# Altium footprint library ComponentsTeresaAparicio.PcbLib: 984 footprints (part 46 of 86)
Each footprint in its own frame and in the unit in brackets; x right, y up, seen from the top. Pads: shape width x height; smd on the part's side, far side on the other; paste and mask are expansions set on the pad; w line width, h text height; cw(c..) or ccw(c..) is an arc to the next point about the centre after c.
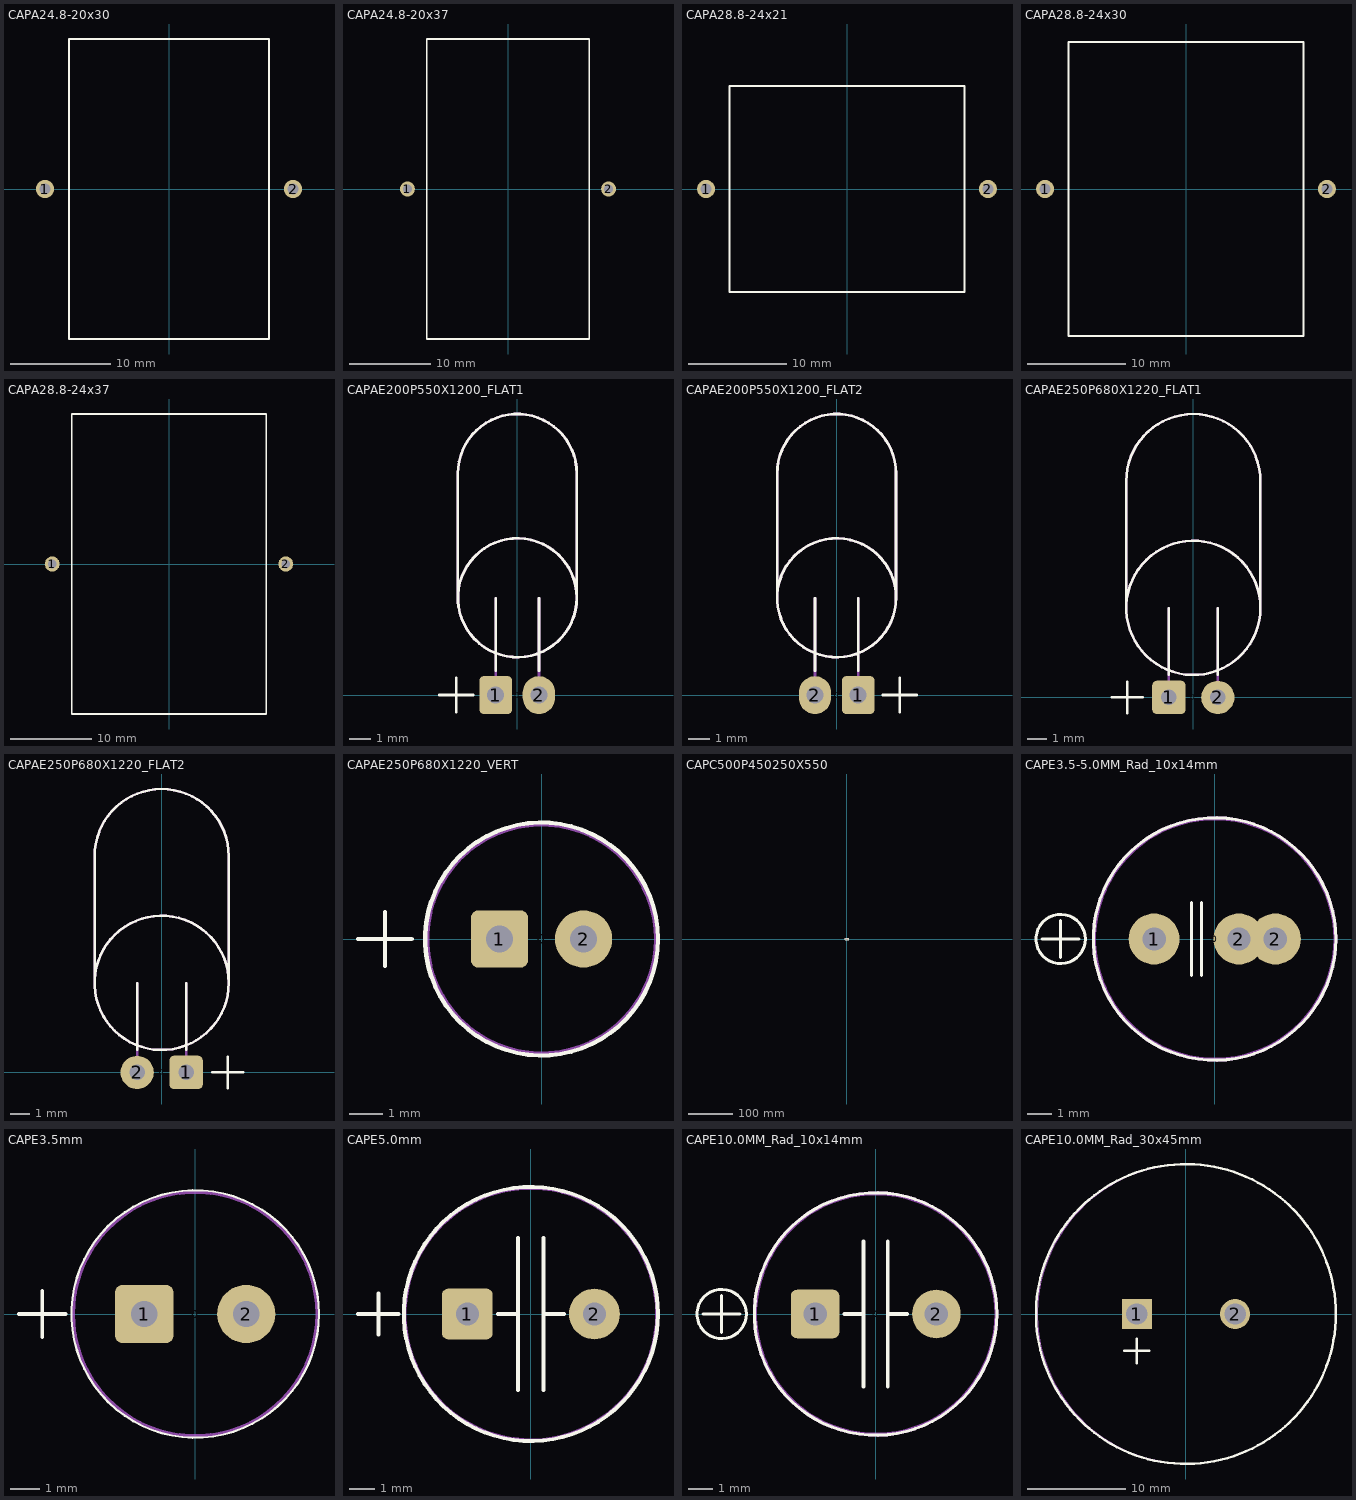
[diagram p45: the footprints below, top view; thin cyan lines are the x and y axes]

## CAPA24.8-20x30 [mm] "Capacitor, Ceramic, Thru-Hole, Axial Leads; Body 20 x 30 mm (LxDia. max) Pin Spacing 24.8 mm (typ)"
height 30
pads (2):
  round 1.85 hole 1.1: 1(-12.4,0) 2(12.4,0)
Top Overlay:
  lines w0.2: -10,-15 10,-15 10,15 -10,15 -10,-15

## CAPA24.8-20x37 [mm] "Capacitor, Ceramic, Thru-Hole, Axial Leads; Body 20 x 37 mm (LxDia. max) Pin Spacing 24.8 mm (typ)"
height 37
pads (2):
  round 1.85 hole 1.1: 1(-12.4,0) 2(12.4,0)
Top Overlay:
  lines w0.2: -10,-18.5 10,-18.5 10,18.5 -10,18.5 -10,-18.5

## CAPA28.8-24x21 [mm] "Capacitor, Ceramic, Thru-Hole, Axial Leads; Body 24 x 21 mm (LxDia. max) Pin Spacing 28.8 mm (typ)"
height 21
pads (2):
  round 1.85 hole 1.1: 1(-14.4,0) 2(14.4,0)
Top Overlay:
  lines w0.2: -12,-10.5 -12,10.5 12,10.5 12,-10.5 -12,-10.5

## CAPA28.8-24x30 [mm] "Capacitor, Ceramic, Thru-Hole, Axial Leads; Body 24 x 30 mm (LxDia. max) Pin Spacing 28.8 mm (typ)"
height 30
pads (2):
  round 1.85 hole 1.1: 1(-14.4,0) 2(14.4,0)
Top Overlay:
  lines w0.2: -12,-15 12,-15 12,15 -12,15 -12,-15

## CAPA28.8-24x37 [mm] "Capacitor, Ceramic, Thru-Hole, Axial Leads; Body 24 x 37 mm (LxDia. max) Pin Spacing 28.8 mm (typ)"
height 37
pads (2):
  round 1.85 hole 1.1: 1(-14.4,0) 2(14.4,0)
Top Overlay:
  lines w0.2: -12,-18.5 -12,18.5 12,18.5 12,-18.5 -12,-18.5

## CAPAE200P550X1200_FLAT1 [mil]
height 216.54
pads (3):
  round 20 on Mech14: 0(0,0)
  rrect25% 60x70 hole 31.5: 1(-40,0)
  oval 60x70 hole 31.5: 2(40,0)
Top Overlay:
  circle w5: c0,180 r110
  lines w5: -144.57,0 -81.57,0 ; -113.07,-31.5 -113.07,31.5 ; -110,180 -110,410 cw(c0,410) 110,410 110,180 ; -40,45 -40,179.21 ; 40,45 40,179.21
Mechanical 13:
  circle w5: c0,180 r110
  lines w5: -110,180 -110,410 cw(c0,410) 110,410 110,180 ; -40,0 -40,179.21 ; 40,0 40,179.21
3D body: height 215.69, standoff -70, extent -107.37,-9.82 107.35,502.05

## CAPAE200P550X1200_FLAT2 [mil]
height 216.54
pads (3):
  round 20 on Mech14: 0(0,0)
  rrect25% 60x70 hole 31.5: 1(40,0)
  oval 60x70 hole 31.5: 2(-40,0)
Top Overlay:
  circle w5: c0,180 r110
  lines w5: -110,180 -110,410 cw(c0,410) 110,410 110,180 ; -40,45 -40,179.21 ; 40,45 40,179.21 ; 85.43,0 148.43,0 ; 116.93,-31.5 116.93,31.5
Mechanical 13:
  circle w5: c0,180 r110
  lines w5: -110,180 -110,410 cw(c0,410) 110,410 110,180 ; -40,0 -40,179.21 ; 40,0 40,179.21
3D body: height 215.69, standoff -70, extent -107.33,-9.82 107.39,502.05

## CAPAE250P680X1220_FLAT1 [mm]
height 6.8
pads (3):
  round 0.508 on Mech14: 0(0,0)
  rrect25% 1.7x1.7 hole 0.8: 1(-1.25,0)
  round 1.7 hole 0.8: 2(1.25,0)
Top Overlay:
  circle w0.127: c0,4.572 r3.429
  lines w0.127: -4.18,0 -2.58,0 ; -3.429,4.572 -3.429,11.049 cw(c0,11.049) 3.429,11.049 3.429,4.572 ; -3.38,-0.8 -3.38,0.8 ; -1.25,1.143 -1.25,4.552 ; 1.25,1.143 1.25,4.552
Mechanical 13:
  circle w0.127: c0,4.572 r3.429
  lines w0.127: -3.429,4.572 -3.429,11.049 cw(c0,11.049) 3.429,11.049 3.429,4.572 ; -1.25,0 -1.25,4.552 ; 1.25,0 1.25,4.552
3D body: height 6.77, standoff -1.78, extent -3.372,-0.249 3.371,12.952

## CAPAE250P680X1220_FLAT2 [mm]
height 6.8
pads (3):
  round 0.508 on Mech14: 0(0,0)
  rrect25% 1.7x1.7 hole 0.8: 1(1.25,0)
  round 1.7 hole 0.8: 2(-1.25,0)
Top Overlay:
  circle w0.127: c0,4.572 r3.429
  lines w0.127: -3.429,4.572 -3.429,11.049 cw(c0,11.049) 3.429,11.049 3.429,4.572 ; -1.25,1.143 -1.25,4.552 ; 1.25,1.143 1.25,4.552 ; 2.58,0 4.18,0 ; 3.38,-0.8 3.38,0.8
Mechanical 13:
  circle w0.127: c0,4.572 r3.429
  lines w0.127: -3.429,4.572 -3.429,11.049 cw(c0,11.049) 3.429,11.049 3.429,4.572 ; -1.25,0 -1.25,4.552 ; 1.25,0 1.25,4.552
3D body: height 6.77, standoff -1.78, extent -3.371,-0.249 3.372,12.952

## CAPAE250P680X1220_VERT [mm]
height 12.2
pads (3):
  round 0.508 on Mech14: 0(0,0)
  rrect25% 1.7x1.7 hole 0.8: 1(-1.25,0)
  round 1.7 hole 0.8: 2(1.25,0)
Top Overlay:
  circle w0.127: c0,0 r3.459
  lines w0.127: -5.45,0 -3.85,0 ; -4.65,-0.8 -4.65,0.8
Mechanical 13:
  circle w0.127: c0,0 r3.4
3D body: height 12.2, standoff -1.78, extent -3.372,-3.372 3.371,3.372

## CAPC500P450250X550 [mm] "TDK FK24 radial ceramic capacitor"
height 5.5
pads (3):
  round 0.508 on Mech14: 0(0,0)
  rrect25% 1.905x1.905 hole 0.8: 1(-2.5,0)
  round 1.905 hole 0.8: 2(2.5,0)
Top Overlay:
  lines w0.127: -3.81,-1.27 3.81,-1.27 3.81,1.27 -3.81,1.27 -3.81,-1.27
Mechanical 13:
  lines w0.127: -2.5,-0.3 cw(c-2.5,0) -2.5,0.3 ; -2.25,-0.523 -2.248,-0.511 -2.24,-0.497 -2.227,-0.48 -2.21,-0.461 -2.186,-0.439 -2.157,-0.415 -2.122,-0.387 -2.083,-0.357 -2.046,-0.327 -2.006,-0.292 -1.995,-0.281 -1.983,-0.268 -1.972,-0.254 -1.962,-0.238 -1.958,-0.229 -1.955,-0.218 -1.954,-0.211 -1.953,-0.203 ; -2.25,0.523 cw(c-3.279,-0.727) -1.953,0.203 ; -2.236,-0.718 cw(c-1.896,-0.22) -2.5,-0.217 -2.5,0.217 cw(c-1.896,0.221) -2.232,0.723 -2.23,0.724 -2.206,0.741 ; -2.232,-0.723 -2.225,-0.727 -2.205,-0.742 ; 2.205,0.742 2.225,0.727 2.232,0.723 ; 2.206,-0.741 2.23,-0.724 2.232,-0.723 ccw(c1.896,-0.221) 2.5,-0.217 2.5,0.217 ccw(c1.896,0.22) 2.236,0.718 ; 2.25,-0.523 2.243,-0.502 2.225,-0.477 2.187,-0.44 2.134,-0.397 2.073,-0.349 2.007,-0.293 1.986,-0.271 1.967,-0.246 1.956,-0.223 1.953,-0.203 ; 2.25,0.523 2.24,0.497 2.21,0.461 2.157,0.415 2.083,0.357 2.046,0.327 2.006,0.292 1.983,0.268 1.962,0.238 1.955,0.218 1.953,0.203 ; 2.5,-0.3 ccw(c2.5,0) 2.5,0.3 ; -1.953,-0.203 -1.953,0.203 ; -1.953,-0.203 1.953,-0.203 ; -1.953,0.203 1.953,0.203 ; -1.8,-1.003 cw(c-1.8,-0.553) -2.25,-0.553 -2.25,0.553 cw(c-1.8,0.553) -1.8,1.003 ; -1.8,-1.003 cw(c-1.777,-0.913) -1.867,-0.935 cw(c9.111,-1.292) -1.819,-0.203 -1.819,0.203 ccw(c-168.083,-10.401) -1.867,0.935 cw(c-1.777,0.912) -1.8,1.003 ; -1.8,-1.003 1.8,-1.003 ; -1.8,1.003 1.8,1.003 ; 1.8,-1.003 ccw(c1.8,-0.553) 2.25,-0.553 2.25,0.553 ccw(c1.8,0.553) 1.8,1.003 ; 1.8,-1.003 ccw(c1.777,-0.912) 1.867,-0.935 cw(c168.269,10.414) 1.819,-0.203 1.819,0.203 ccw(c-9.111,1.292) 1.867,0.935 ccw(c1.777,0.913) 1.8,1.003 ; 1.953,-0.203 1.953,0.203
3D body: height 5.47, standoff -2.54, extent -2.797,-1.003 2.798,1.003

## CAPE3.5-5.0MM_Rad_10x14mm [mm] "3.5 & 5.0mm Pitch Radial Capacitor 10x14mm DxH"
height 14
pads (4):
  round 0.5 on Mech14: 0(0,0)
  round 2.1 hole 0.965: 1(-2.5,0) 2(1,0) 2(2.5,0)
Top Overlay:
  circle w0.127: c0,0 r5
  circle w0.127: c-6.35,0 r1.016
  lines w0.127: -7.112,0 -5.588,0 ; -6.35,-0.762 -6.35,0.762 ; -0.95,-1.5 -0.95,1.5 ; -0.55,-1.5 -0.55,1.5
Mechanical 13:
  circle w0.127: c0,0 r4.953
Mechanical 14:
  circle w0.127: c0,0 r5
3D body: height 13.99, standoff -3.51, extent -5.25,-5.237 5.206,5.237

## CAPE3.5mm [mm]
pads (3):
  round 0.508 on Mech14: 0(0,0)
  rrect25% 2x2 hole 0.9: 1(-1.75,0)
  round 2 hole 0.9: 2(1.75,0)
Top Overlay:
  circle w0.076: c0,0 r4.25
  lines w0.127: -6.05,0 -4.45,0 ; -5.25,-0.8 -5.25,0.8
Mechanical 13:
  circle w0.127: c0,0 r4.191
3D body: height 7.1, standoff 0.1, extent -4.25,-4.25 4.216,4.233

## CAPE5.0mm [mm]
height 20
pads (2):
  rrect25% 2x2 hole 0.9: 1(-2.5,0)
  round 2 hole 0.9: 2(2.5,0)
Top Overlay:
  circle w0.152: c0,0 r5
  lines w0.152: -6.8,0 -5.2,0 ; -6,-0.8 -6,0.8 ; -1.3,0 -0.5,0 ; -0.5,-3 -0.5,3 ; 0.5,-3 0.5,3 ; 0.5,0 1.3,0
Mechanical 13:
  circle w0.127: c0,-0.003 r4.953
3D body: height 20, standoff -3.5, extent -4.958,-4.968 4.953,4.961

## CAPE10.0MM_Rad_10x14mm [mm] "10mm Pitch Radial Capacitor 10x14mm DxH"
height 14
pads (3):
  round 0.5 on Mech14: 0(0,0)
  rrect25% 2x2 hole 0.965: 1(-2.5,0)
  round 2 hole 0.965: 2(2.5,0)
Top Overlay:
  circle w0.127: c-6.35,0 r1.016
  circle w0.127: c0,0 r5
  lines w0.127: -7.112,0 -5.588,0 ; -6.35,-0.762 -6.35,0.762
  lines w0.152: -1.3,0.003 -0.5,0.003 ; -0.5,-2.997 -0.5,3.003 ; 0.5,-2.997 0.5,3.003 ; 0.5,0.003 1.3,0.003
Mechanical 13:
  circle w0.127: c0,0 r4.953
Mechanical 14:
  circle w0.127: c0,0 r5
3D body: height 13.99, standoff -3.51, extent -5.25,-5.237 5.206,5.237

## CAPE10.0MM_Rad_30x45mm [mil] "10mm Pitch Radial Capacitor"
height 1771.65
pads (2):
  rect 120x120 hole 86: 1(-196.85,0)
  round 120 hole 86: 2(196.85,0)
Top Overlay:
  circle w10: c0,0 r600.39
  lines w10: -246.06,-147.64 -147.64,-147.64 ; -196.85,-196.85 -196.85,-98.43
Mechanical 15:
  circle w5: c3.15,0 r597.8
3D body: height 1771.65, standoff -137.8, extent -585.73,-588.1 589.23,588.11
